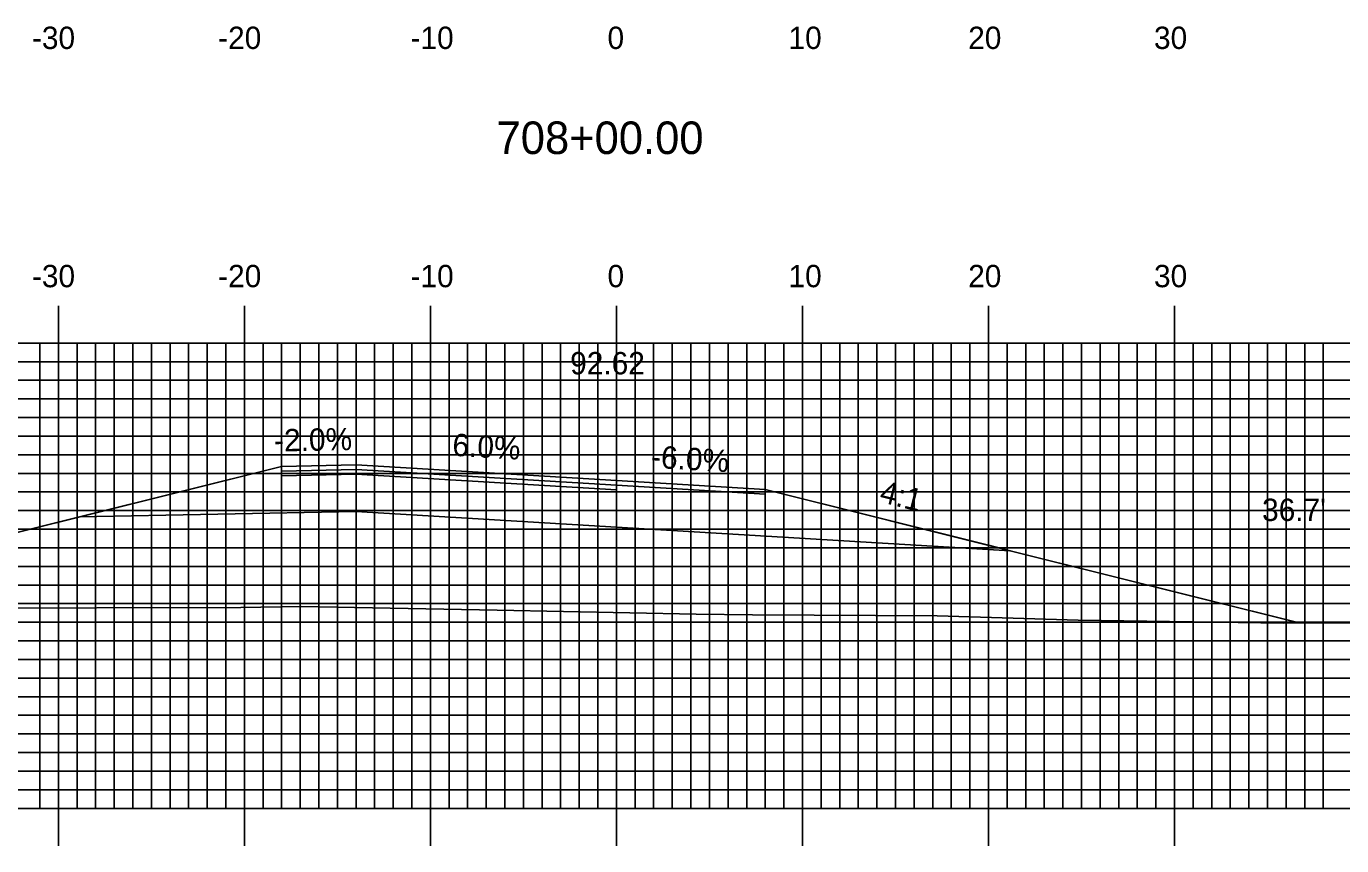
# Model space of a CAD drawing. Extents: x 854116 to 854460, y 364366 to 364586.
# Drawn here: x 854250.5 to 854321.2, y 364471.8 to 364515.8 of the extents above; entities that cross this region are included whole.
import ezdxf

# ---------------------------------------------------------------- set-up
doc = ezdxf.new("R2010")
doc.units = 0
for name, color, linetype in [('ANNOTATION', 7, 'Continuous'), ('D_Roadway_Centerline', 7, 'Continuous'), ('D_Roadway_Centerline_Text', 7, 'Continuous'), ('D_Roadway_Edge_Shoulder', 7, 'Continuous'), ('D_Roadway_Edge_TW', 7, 'Continuous'), ('D_Roadway_Pavement', 7, 'Continuous'), ('D_Roadway_SlopeLines', 7, 'Continuous'), ('D_Roadway_SubGrade', 7, 'Continuous'), ('D_Text_Standard', 7, 'Continuous'), ('H_V ANNOTATION', 7, 'Continuous'), ('MAJOR', 7, 'Continuous'), ('MINOR', 7, 'Continuous'), ('S_Roadway_Centerline', 7, 'Continuous')]:
    doc.layers.add(name, color=color, linetype=linetype)

msp = doc.modelspace()

# ---------------------------------------------------------------- linework, layer by layer
at = {"layer": 'D_Roadway_Centerline'}
msp.add_lwpolyline([(854239.887, 364486.076), (854253.361, 364489.445), (854264.231, 364492.162), (854268.231, 364492.242), (854282.231, 364491.402), (854290.231, 364490.922), (854302.231, 364487.922), (854303.389, 364487.633), (854318.771, 364483.787)], dxfattribs=at)
at = {"layer": 'D_Roadway_Edge_Shoulder'}
for points in [[(854268.231, 364492.242), (854264.231, 364492.162), (854264.231, 364491.912), (854268.231, 364491.992)], [(854282.231, 364491.402), (854290.231, 364490.922), (854290.231, 364490.672), (854282.231, 364491.152)]]:
    msp.add_lwpolyline(points, close=True, dxfattribs=at)
at = {"layer": 'D_Roadway_Edge_TW'}
msp.add_lwpolyline([(854268.231, 364492.242), (854282.231, 364491.402), (854282.231, 364491.152), (854268.231, 364491.992)], close=True, dxfattribs=at)
at = {"layer": 'D_Roadway_Pavement'}
for points in [[(854268.231, 364491.992), (854264.231, 364491.912), (854264.231, 364491.662), (854268.231, 364491.742)], [(854268.231, 364491.992), (854282.231, 364491.152), (854282.231, 364490.902), (854268.231, 364491.742)]]:
    msp.add_lwpolyline(points, close=True, dxfattribs=at)
msp.add_lwpolyline([(854282.231, 364491.152), (854282.231, 364490.902)], dxfattribs=at)
msp.add_lwpolyline([(854282.231, 364491.152), (854282.231, 364490.902)], dxfattribs=at)
at = {"layer": 'D_Roadway_SlopeLines'}
for points in [[(854264.231, 364492.162), (854239.887, 364486.076)], [(854290.231, 364490.922), (854303.389, 364487.633), (854318.928, 364483.748)]]:
    msp.add_lwpolyline(points, dxfattribs=at)
at = {"layer": 'D_Roadway_SubGrade'}
for points in [[(854268.231, 364491.742), (854264.231, 364491.662), (854264.231, 364491.912), (854264.231, 364492.162), (854253.361, 364489.445), (854268.231, 364489.742)], [(854268.231, 364491.742), (854282.231, 364490.902), (854282.231, 364488.902), (854268.231, 364489.742)], [(854282.231, 364490.902), (854282.231, 364491.152), (854290.231, 364490.672), (854290.231, 364490.922), (854303.389, 364487.633), (854282.231, 364488.902)]]:
    msp.add_lwpolyline(points, close=True, dxfattribs=at)
at = {"layer": 'MAJOR'}
for p, q in [((854252.231, 364500.791), (854252.231, 364498.787)), ((854262.231, 364500.791), (854262.231, 364498.787)), ((854272.231, 364500.791), (854272.231, 364498.787)), ((854282.231, 364500.791), (854282.231, 364498.787)), ((854292.231, 364500.791), (854292.231, 364498.787)), ((854302.231, 364500.791), (854302.231, 364498.787)), ((854312.231, 364500.791), (854312.231, 364498.787)), ((854142.231, 364498.787), (854422.231, 364498.787)), ((854142.231, 364498.787), (854422.231, 364498.787)), ((854252.231, 364473.787), (854252.231, 364498.787)), ((854262.231, 364473.787), (854262.231, 364498.787)), ((854272.231, 364473.787), (854272.231, 364498.787)), ((854282.231, 364473.787), (854282.231, 364498.787)), ((854292.231, 364473.787), (854292.231, 364498.787)), ((854302.231, 364473.787), (854302.231, 364498.787)), ((854312.231, 364473.787), (854312.231, 364498.787)), ((854142.231, 364493.787), (854422.231, 364493.787)), ((854142.231, 364488.787), (854422.231, 364488.787)), ((854142.231, 364483.787), (854422.231, 364483.787)), ((854142.231, 364478.787), (854422.231, 364478.787)), ((854142.231, 364473.787), (854422.231, 364473.787)), ((854142.231, 364473.787), (854422.231, 364473.787)), ((854252.231, 364471.783), (854252.231, 364473.787)), ((854262.231, 364471.783), (854262.231, 364473.787)), ((854272.231, 364471.783), (854272.231, 364473.787)), ((854282.231, 364471.783), (854282.231, 364473.787)), ((854292.231, 364471.783), (854292.231, 364473.787)), ((854302.231, 364471.783), (854302.231, 364473.787)), ((854312.231, 364471.783), (854312.231, 364473.787))]:
    msp.add_line(p, q, dxfattribs=at)
at = {"layer": 'MINOR'}
for p, q in [((854251.231, 364473.787), (854251.231, 364498.787)), ((854253.231, 364473.787), (854253.231, 364498.787)), ((854254.231, 364473.787), (854254.231, 364498.787)), ((854255.231, 364473.787), (854255.231, 364498.787)), ((854256.231, 364473.787), (854256.231, 364498.787)), ((854257.231, 364473.787), (854257.231, 364498.787)), ((854258.231, 364473.787), (854258.231, 364498.787)), ((854259.231, 364473.787), (854259.231, 364498.787)), ((854260.231, 364473.787), (854260.231, 364498.787)), ((854261.231, 364473.787), (854261.231, 364498.787)), ((854263.231, 364473.787), (854263.231, 364498.787)), ((854264.231, 364473.787), (854264.231, 364498.787)), ((854265.231, 364473.787), (854265.231, 364498.787)), ((854266.231, 364473.787), (854266.231, 364498.787)), ((854267.231, 364473.787), (854267.231, 364498.787)), ((854268.231, 364473.787), (854268.231, 364498.787)), ((854269.231, 364473.787), (854269.231, 364498.787)), ((854270.231, 364473.787), (854270.231, 364498.787)), ((854271.231, 364473.787), (854271.231, 364498.787)), ((854273.231, 364473.787), (854273.231, 364498.787)), ((854274.231, 364473.787), (854274.231, 364498.787)), ((854275.231, 364473.787), (854275.231, 364498.787)), ((854276.231, 364473.787), (854276.231, 364498.787)), ((854277.231, 364473.787), (854277.231, 364498.787)), ((854278.231, 364473.787), (854278.231, 364498.787)), ((854279.231, 364473.787), (854279.231, 364498.787)), ((854280.231, 364473.787), (854280.231, 364498.787)), ((854281.231, 364473.787), (854281.231, 364498.787)), ((854283.231, 364473.787), (854283.231, 364498.787)), ((854284.231, 364473.787), (854284.231, 364498.787)), ((854285.231, 364473.787), (854285.231, 364498.787)), ((854286.231, 364473.787), (854286.231, 364498.787)), ((854287.231, 364473.787), (854287.231, 364498.787)), ((854288.231, 364473.787), (854288.231, 364498.787)), ((854289.231, 364473.787), (854289.231, 364498.787)), ((854290.231, 364473.787), (854290.231, 364498.787)), ((854291.231, 364473.787), (854291.231, 364498.787)), ((854293.231, 364473.787), (854293.231, 364498.787)), ((854294.231, 364473.787), (854294.231, 364498.787)), ((854295.231, 364473.787), (854295.231, 364498.787)), ((854296.231, 364473.787), (854296.231, 364498.787)), ((854297.231, 364473.787), (854297.231, 364498.787)), ((854298.231, 364473.787), (854298.231, 364498.787)), ((854299.231, 364473.787), (854299.231, 364498.787)), ((854300.231, 364473.787), (854300.231, 364498.787)), ((854301.231, 364473.787), (854301.231, 364498.787)), ((854303.231, 364473.787), (854303.231, 364498.787)), ((854304.231, 364473.787), (854304.231, 364498.787)), ((854305.231, 364473.787), (854305.231, 364498.787)), ((854306.231, 364473.787), (854306.231, 364498.787)), ((854307.231, 364473.787), (854307.231, 364498.787)), ((854308.231, 364473.787), (854308.231, 364498.787)), ((854309.231, 364473.787), (854309.231, 364498.787)), ((854310.231, 364473.787), (854310.231, 364498.787)), ((854311.231, 364473.787), (854311.231, 364498.787)), ((854313.231, 364473.787), (854313.231, 364498.787)), ((854314.231, 364473.787), (854314.231, 364498.787)), ((854315.231, 364473.787), (854315.231, 364498.787)), ((854316.231, 364473.787), (854316.231, 364498.787)), ((854317.231, 364473.787), (854317.231, 364498.787)), ((854318.231, 364473.787), (854318.231, 364498.787)), ((854319.231, 364473.787), (854319.231, 364498.787)), ((854320.231, 364473.787), (854320.231, 364498.787)), ((854142.231, 364497.787), (854422.231, 364497.787)), ((854142.231, 364496.787), (854422.231, 364496.787)), ((854142.231, 364495.787), (854422.231, 364495.787)), ((854142.231, 364494.787), (854422.231, 364494.787)), ((854142.231, 364492.787), (854422.231, 364492.787)), ((854142.231, 364491.787), (854422.231, 364491.787)), ((854142.231, 364490.787), (854422.231, 364490.787)), ((854142.231, 364489.787), (854422.231, 364489.787)), ((854142.231, 364487.787), (854422.231, 364487.787)), ((854142.231, 364486.787), (854422.231, 364486.787)), ((854142.231, 364485.787), (854422.231, 364485.787)), ((854142.231, 364484.787), (854422.231, 364484.787)), ((854142.231, 364482.787), (854422.231, 364482.787)), ((854142.231, 364481.787), (854422.231, 364481.787)), ((854142.231, 364480.787), (854422.231, 364480.787)), ((854142.231, 364479.787), (854422.231, 364479.787)), ((854142.231, 364477.787), (854422.231, 364477.787)), ((854142.231, 364476.787), (854422.231, 364476.787)), ((854142.231, 364475.787), (854422.231, 364475.787)), ((854142.231, 364474.787), (854422.231, 364474.787))]:
    msp.add_line(p, q, dxfattribs=at)
at = {"layer": 'S_Roadway_Centerline'}
msp.add_lwpolyline([(854142.231, 364484.511), (854145.429, 364484.528), (854150.306, 364484.555), (854166.246, 364484.591), (854170.894, 364484.603), (854177.648, 364484.664), (854184.53, 364484.683), (854193.853, 364484.725), (854205.158, 364484.77), (854206.428, 364484.761), (854208.948, 364484.742), (854225.488, 364484.594), (854233.755, 364484.604), (854246.526, 364484.542), (854262.03, 364484.588), (854265.279, 364484.626), (854275.818, 364484.443), (854286.51, 364484.214), (854289.541, 364484.192), (854299.468, 364484.135), (854307.051, 364483.895), (854318.102, 364483.745), (854326.025, 364483.773)], dxfattribs=at)

# ---------------------------------------------------------------- texts
at = {"layer": 'ANNOTATION'}
for s, rotation, p in [('-2.0%', 1.14576, (854263.837, 364492.955)), ('6.0%', 356.56637, (854273.385, 364492.737)), ('-6.0%', 356.56637, (854284.065, 364492.096)), ('4:1', 345.96376, (854296.315, 364490.263))]:
    msp.add_text(s, height=1.2, rotation=rotation, dxfattribs=at).set_placement(p)
at = {"layer": 'D_Roadway_Centerline_Text'}
msp.add_text('92.62', height=1.2, dxfattribs=at).set_placement((854279.742, 364497.106))
at = {"layer": 'D_Text_Standard'}
msp.add_text("36.7'", height=1.2, dxfattribs=at).set_placement((854316.938, 364489.228))
at = {"layer": 'H_V ANNOTATION'}
for s, height, p in [('-30', 1.2, (854250.807, 364514.587)), ('-20', 1.2, (854260.818, 364514.587)), ('-10', 1.2, (854271.16, 364514.587)), ('0', 1.2, (854281.749, 364514.587)), ('10', 1.2, (854291.481, 364514.587)), ('20', 1.2, (854301.139, 364514.587)), ('30', 1.2, (854311.128, 364514.587)), ('708+00.00', 1.75, (854275.785, 364508.943)), ('-30', 1.2, (854250.807, 364501.787)), ('-20', 1.2, (854260.818, 364501.787)), ('-10', 1.2, (854271.16, 364501.787)), ('0', 1.2, (854281.749, 364501.787)), ('10', 1.2, (854291.481, 364501.787)), ('20', 1.2, (854301.139, 364501.787)), ('30', 1.2, (854311.128, 364501.787))]:
    msp.add_text(s, height=height, dxfattribs=at).set_placement(p)

doc.saveas('drawing.dxf')
